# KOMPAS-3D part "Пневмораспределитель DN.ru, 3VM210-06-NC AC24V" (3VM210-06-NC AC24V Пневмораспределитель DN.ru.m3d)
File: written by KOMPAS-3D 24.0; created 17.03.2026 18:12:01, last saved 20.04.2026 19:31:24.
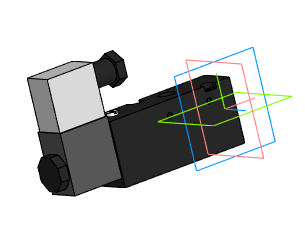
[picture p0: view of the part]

Document properties: Автор: R2D2; Полное имя файла: 3VM210-06-NC AC24V Пневмораспредели тель DN.ru.cdw

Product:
- Part/product: Пневмораспределитель DN.ru  | designation 3VM210-06-NC AC24V
    Масса: 0.3
    Раздел спецификации: Прочие изделия
    Форматы листов документа: A3
    Примечание: D290-00378

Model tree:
1. Операция без истории:3

Expressions: 3VM210-06-NC AC24V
